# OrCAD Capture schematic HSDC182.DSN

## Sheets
1 PAGE1: size C; title: TUSB2E221QFNEVM; rev: A; note: HSDC182
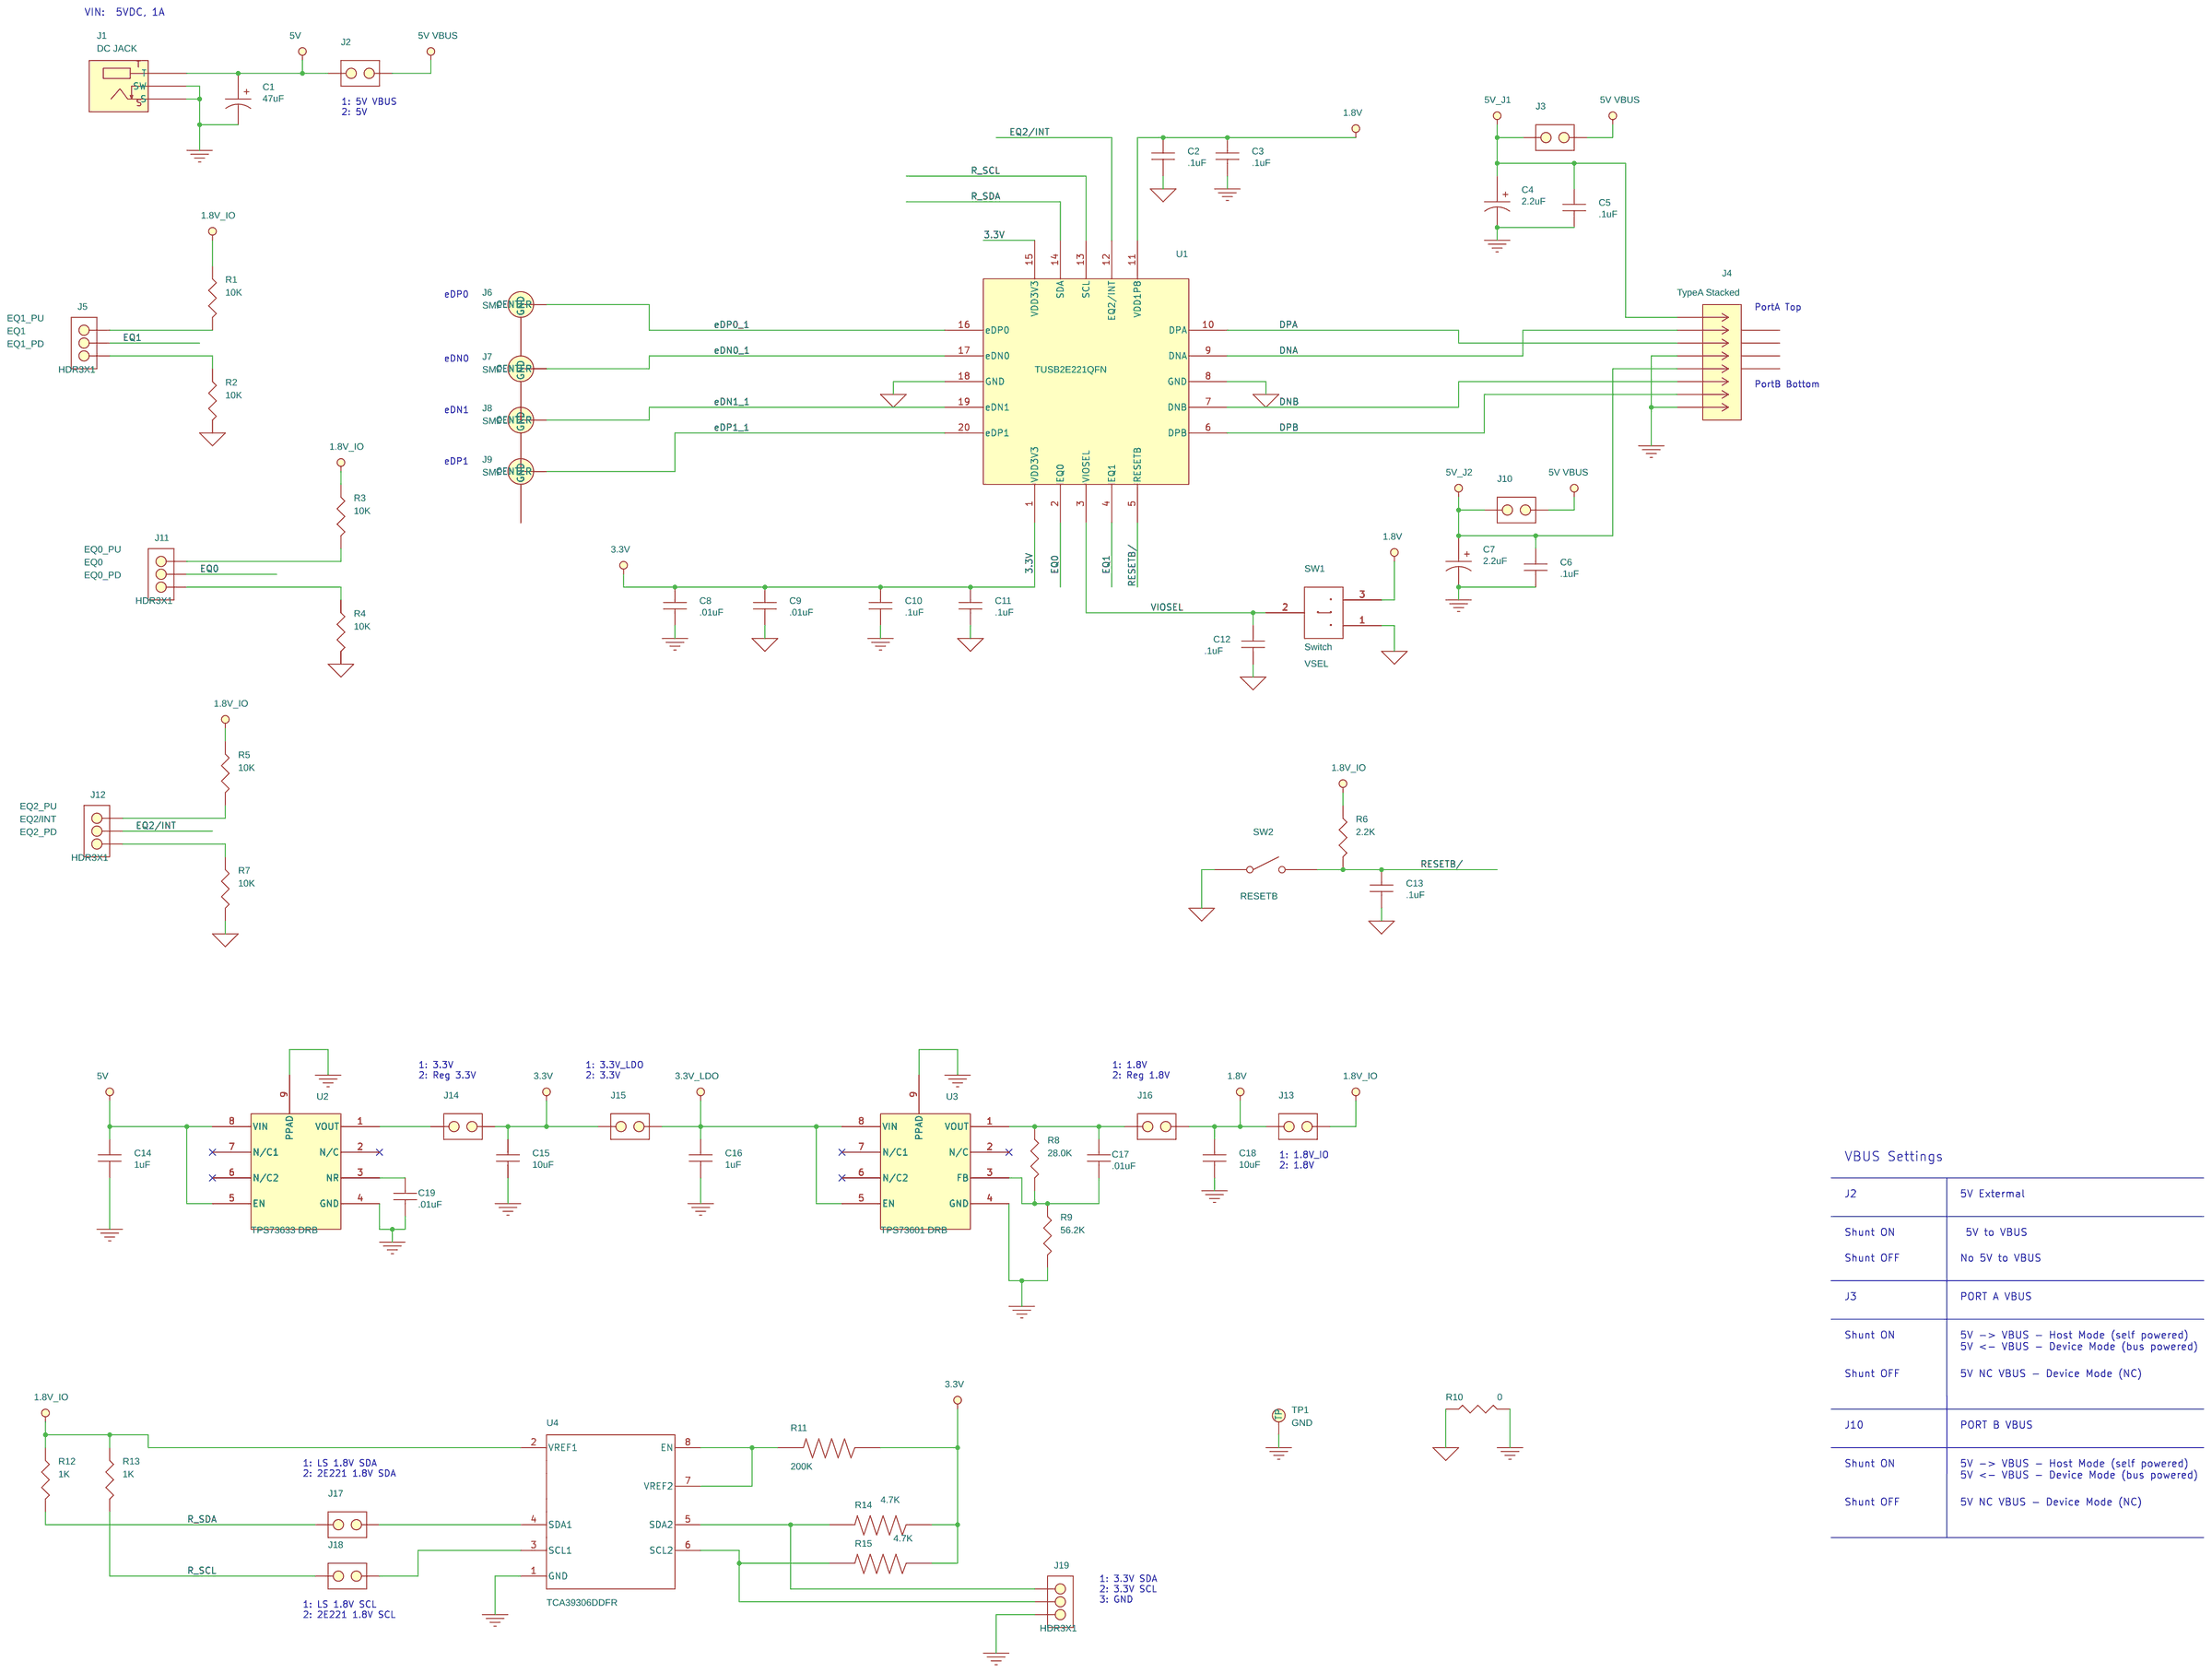
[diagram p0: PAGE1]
2 PAGE2
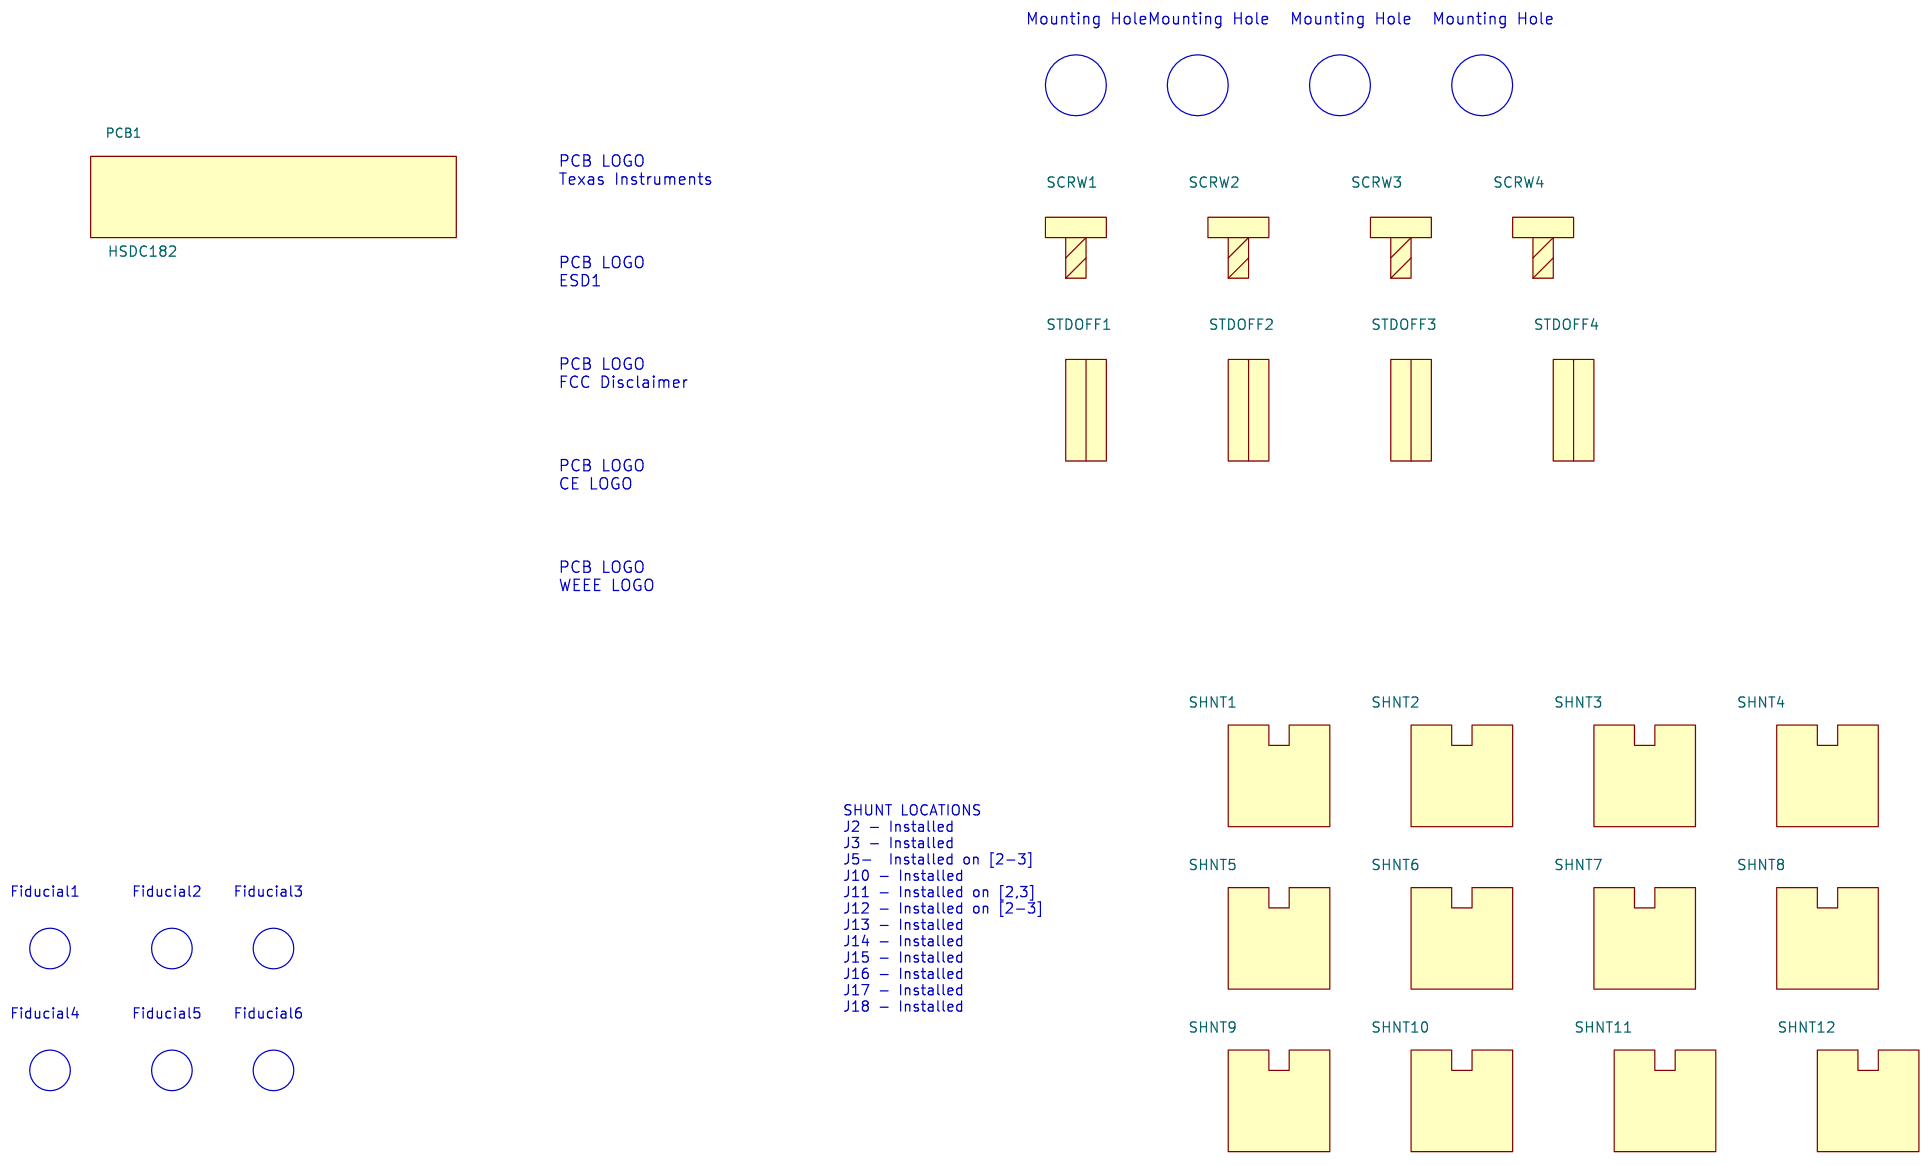
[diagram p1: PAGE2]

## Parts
sheet PAGE1
C1  47uF  [cap_1210]
C2  .1uF  [cap_0402]
C3  .1uF  [cap_0402]
C4  2.2uF  [cap_0805]
C5  .1uF  [cap_0402]
C6  .1uF  [cap_0402]
C7  2.2uF  [cap_0805]
C8  .01uF  [cap_0402]
C9  .01uF  [cap_0402]
C10  .1uF  [cap_0402]
C11  .1uF  [cap_0402]
C12  .1uF  [cap_0402]
C13  .1uF  [cap_0402]
C14  1uF  [cap_0805]
C15  10uF  [cap_0805]
C16  1uF  [cap_0805]
C17  .01uF  [cap_0402]
C18  10uF  [cap_0805]
C19  .01uF  [cap_0402]
J1  DC JACK  [JACK_SMRT_PJ1-022-SMT-TR]
J2  HDR2X1  [HDR_THVT_1X2_254_871]
J3  HDR2X1  [HDR_THVT_1X2_254_871]
J4  TypeA Stacked  [USB-A_THRT_AU-Y1008-2]
J5  HDR3X1  [HDR_THVT_1X3_254_871]
J6  SMP  [CON_SMRT_19S201-40ML5]
J7  SMP  [CON_SMRT_19S201-40ML5]
J8  SMP  [CON_SMRT_19S201-40ML5]
J9  SMP  [CON_SMRT_19S201-40ML5]
J10  HDR2X1  [HDR_THVT_1X2_254_871]
J11  HDR3X1  [HDR_THVT_1X3_254_871]
J12  HDR3X1  [HDR_THVT_1X3_254_871]
J13  HDR2X1  [HDR_THVT_1X2_254_871]
J14  HDR2X1  [HDR_THVT_1X2_254_871]
J15  HDR2X1  [HDR_THVT_1X2_254_871]
J16  HDR2X1  [HDR_THVT_1X2_254_871]
J17  HDR2X1  [HDR_THVT_1X2_254_871]
J18  HDR2X1  [HDR_THVT_1X2_254_871]
J19  HDR3X1  [HDR_THVT_1X3_254_871]
R1  10K  [res_0402]
R2  10K  [res_0402]
R3  10K  [res_0402]
R4  10K  [res_0402]
R5  10K  [res_0402]
R6  2.2K  [res_0402]
R7  10K  [res_0402]
R8  28.0K  [res_0402]
R9  56.2K  [res_0402]
R10  0  [res_0805]
R11  200K  [RES_0402]
R12  1K  [res_0402]
R13  1K  [res_0402]
R14  4.7K  [RES_0402]
R15  4.7K  [RES_0402]
SW1  Switch  [SW_SMVT_CJS-1201B]
SW2  RESETB  [SW_SMVT_B3U-1000P]
TP1  TEST POINT  [HDR_THVT_1X1_871]
U1  TUSB2E221QFN  [VBW0020A]
U2  TPS73633 DRB  [DRB0008BA_150x175]
U3  TPS73601 DRB  [DRB0008BA_150x175]
U4  TCA39306DDFR  [DDF0008A]
sheet PAGE2
PCB1  HSDC182  [n/a]
SCRW1  NY PMS 440 005 PH  [screw]
SCRW2  NY PMS 440 005 PH  [screw]
SCRW3  NY PMS 440 005 PH  [screw]
SCRW4  NY PMS 440 005 PH  [screw]
SHNT1  QPC02SXGN-RC  [.1]
SHNT2  QPC02SXGN-RC  [.1]
SHNT3  QPC02SXGN-RC  [.1]
SHNT4  QPC02SXGN-RC  [.1]
SHNT5  QPC02SXGN-RC  [.1]
SHNT6  QPC02SXGN-RC  [.1]
SHNT7  QPC02SXGN-RC  [.1]
SHNT8  QPC02SXGN-RC  [.1]
SHNT9  QPC02SXGN-RC  [.1]
SHNT10  QPC02SXGN-RC  [.1]
SHNT11  QPC02SXGN-RC  [.1]
SHNT12  QPC02SXGN-RC  [.1]
STDOFF1  1902E  [Standoff]
STDOFF2  1902E  [Standoff]
STDOFF3  1902E  [Standoff]
STDOFF4  1902E  [Standoff]

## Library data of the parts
C1 = CAPACITOR_POL: Digikey: 445-6711-2-ND; Manufacturer: TDK; Manufacturer Part Number: C3225X5R1A476M250AC; SIGNAL_MODEL: DEFAULT_CAPACITOR_4.7e+07pF_1_2
C2 C3 C5 C6 C10-C13 = CAP_NP: Digikey: 311-1336-1-ND; Manufacturer: Yageo; Manufacturer Part Number: CC0402KRX5R6BB104; SIGNAL_MODEL: DEFAULT_CAPACITOR_100000pF_1_2
C4 = CAPACITOR_POL: Digikey: 445-5691-2-ND; Manufacturer: TDK; Manufacturer Part Number: CGA4J3X7R1C225K125AB; SIGNAL_MODEL: DEFAULT_CAPACITOR_2.2e+06pF_1_2
C7 = CAPACITOR_POL: Digikey: 445-5691-2-ND; Diigkey: 445-5691-2-ND; Manufacturer: TDK; Manufacturer Part Number: CGA4J3X7R1C225K125AB; SIGNAL_MODEL: DEFAULT_CAPACITOR_2.2e+06pF_1_2
C8 = CAP_NP: Digikey: 399-1278-2-ND; Diigkey: 399-1278-2-ND; Manufacturer: Kemet; Manufacturer Part Number: C0402C103K3RACTU; SIGNAL_MODEL: DEFAULT_CAPACITOR_10000pF_1_2
C9 C17 C19 = CAP_NP: Digikey: 399-1278-2-ND; Manufacturer: Kemet; Manufacturer Part Number: C0402C103K3RACTU; SIGNAL_MODEL: DEFAULT_CAPACITOR_10000pF_1_2
C14 = CAP_NP: Digikey: 399-1284-2-ND; Manufacturer: Kemet; Manufacturer Part Number: C0805C105K4RACTU; SIGNAL_MODEL: DEFAULT_CAPACITOR_1e+06pF_1_2
C15 C18 = CAP_NP: Digikey: 399-4925-1-ND; Manufacturer: Kemet; Manufacturer Part Number: C0805C106K8PACTU; SIGNAL_MODEL: DEFAULT_CAPACITOR_1e+07pF_1_2
C16 = CAP_NP: Digikey: 399-1284-2-ND; Diigkey: 399-1284-2-ND; Manufacturer: Kemet; Manufacturer Part Number: C0805C105K4RACTU; SIGNAL_MODEL: DEFAULT_CAPACITOR_1e+06pF_1_2
J1 = PWR_JACK: Digikey: CP1-022PJTR-ND; Manufacturer: CUI; Manufacturer Part Number: PJ1-022-SMT-TR
J2 J3 J10 J13-J18 = HDR2X1_M_.1: Digikey: S1012E-02-ND; Manufacturer: Sullins; Manufacturer Part Number: PEC02SAAN
J4 = AU-Y1008-2_0
J5 = HDR3X1_M_.1: Digikey: S1012E-03-ND; Manufacturer: Sullins; Manufacturer Part number: PEC03SAAN; SILKTEXT1: EQ1_PU; SILKTEXT2: EQ1; SILKTEXT3: EQ1_PD
J6-J9 = SMB_0: Digikey: 1868-1133-ND; Manufacturer: Rosenberger; Manufacturer Part Number: 19S201-40ML5
J11 = HDR3X1_M_.1: Digikey: S1012E-03-ND; Manufacturer: Sullins; Manufacturer Part number: PEC03SAAN; SILKTEXT1: EQ0_PU; SILKTEXT2: EQ0; SILKTEXT3: EQ0_PD
J12 = HDR3X1_M_.1: Digikey: S1012E-03-ND; Manufacturer: Sullins; Manufacturer Part number: PEC03SAAN; SILKTEXT1: EQ2_PU; SILKTEXT2: EQ2/INT; SILKTEXT3: EQ2_PD
J19 = HDR3X1_M_.1: Digikey: S1012E-03-ND; Manufacturer: Sullins; Manufacturer Part number: PEC03SAAN; SILKTEXT1: 1: SDA; SILKTEXT2: 2: SCL; SILKTEXT3: 3: GND
R1-R5 R7 = RES: Digikey: 311-10KJRTR-ND; Manufacturer: Yageo; Manufacturer Part Number: RC0402JR-0710KL; SIGNAL_MODEL: DEFAULT_RESISTOR_10000OHM_1_2
R6 = RES: Digikey: 311-2.20KLRTR-ND; Manufacturer: Yageo; Manufacturer Part Number: RC0402FR-072K2L; SIGNAL_MODEL: DEFAULT_RESISTOR_2200OHM_1_2
R8 = RES: Digikey: 311-28.0KLRTR-ND; Manufacturer: Yageo; Manufacturer Part Number: RC0402FR-0728KL; SIGNAL_MODEL: DEFAULT_RESISTOR_28000OHM_1_2
R9 = RES: Digikey: YAG1453TR-ND; Manufacturer: Yageo; Manufacturer Part Number: RT0402BRD0756K2; SIGNAL_MODEL: DEFAULT_RESISTOR_56200OHM_1_2
R10 = RES: Digikey: 311-0.0ARTR-ND; Manufacturer: Yageo; Manufacturer Part Number: RC0805JR-070RL; SIGNAL_MODEL: DEFAULT_RESISTOR_0.001OHM_1_2
R11 = SG73P1ETTP2003D: MANUFACTURER: YAGEO; Manufacturer's Part Number: RC0603FR-07200KL
R12 R13 = RES: Digikey: YAG2306TR-ND; Manufacturer: Yageo; Manufacturer Part Number: RT0402BRE071KL; SIGNAL_MODEL: DEFAULT_RESISTOR_1000.000000OHM_1_2
R14 R15 = RC0402JR-074K7L: MANUFACTURER: YAGEO; Manufacturer's Part Number: RC0603FR-074K7L
SW1 = Switch_CJS-1201: Digikey: 563-1024-1-ND; Manufacturer: Nidec Copal; Manufacturer Part Number: CJS-1201TB; SILKTEXT: VSEL
SW2 = SW_KEY-SPST: Digikey: SW1020CT-ND; Manufacturer: OMRON; Manufacturer Part Number: B3U-1000P
TP1 = Test_Point_Small: Digikey: S1012E-01-ND; Manufacturer: Sullins; Manufacturer Part Number: PEC01SAAN; SILKTEXT: GND
U1 = TUSB2E221QFN: Manufacturer: Texas Instruments
U2 = TPS736_DRB_3: Digikey: 296-17884-1-ND; Manufacturer: Texas Instruments; Manufacturer Part Number: TPS73633DRB
U3 = TPS736_DRB_4: Digikey: 296-27062-1-ND; Manufacturer: Texas Instruments; Manufacturer Part Number: TPS73601DRB
U4 = TCA39306DDFR_0: MANUFACTURER: Texas Instruments
PCB1 = PCB: Manufacturer: Any; Manufacturer Part Number: HSDC124
SCRW1-SCRW4 = Screw_40x.5_Nylon: Digikey: H546-ND; Manufacturer: B&F Fastener; Manufacturer Part Number: NY PMS 440 0050 PH
SHNT1-SHNT12 = Shunt: Digikey: S9337-ND; Manufacturer: Sullins
STDOFF1-STDOFF4 = Standoff: Digikey: 36-1902E-ND; Manufacturer: Keystone

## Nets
1.8V: C2.1 C3.1 C18.1 J13.2 J16.1 SW1.3 U1.11(VDD1P8)
1.8V_IO: J13.1 R1.1 R3.1 R5.1 R6.1 R12.1 R13.1 U4.2(VREF1)
3.3V: C8.1 C9.1 C10.1 C11.1 C15.1 J14.1 J15.2 R11.2 R14.2 R15.2 U1.1(VDD3V3) U1.15(VDD3V3)
3.3V_LDO: C16.1 J15.1 U3.5(EN) U3.8(VIN)
5V: C1.1 C14.1 J1.1(T) J2.2 U2.5(EN) U2.8(VIN)
5V VBUS: J2.1 J3.1 J10.1
5V_J1: C4.1 C5.1 J3.2 J4.1
5V_J2: C6.1 C7.1 J4.5 J10.2
GND: C1.2 C3.2 C4.2 C5.2 C6.2 C7.2 C8.2 C10.2 C14.2 C15.2 C16.2 C18.2 C19.2 J1.2(S) J1.3(SW) J4.4 J4.8 J6.2(GND) J7.2(GND) J8.2(GND) J9.2(GND) J19.3 R9.2 R10.2 TP1.1(TP) U2.4(GND) U2.9(PPAD) U3.4(GND) U3.9(PPAD) U4.1(GND)
GND_SIGNAL: C2.2 C9.2 C11.2 C12.2 C13.2 R2.2 R4.2 R7.2 R10.1 SW1.1 SW2.1 U1.8(GND) U1.18(GND)
DNA: J4.2 U1.9(DNA)
DNB: J4.6 U1.7(DNB)
DPA: J4.3 U1.10(DPA)
DPB: J4.7 U1.6(DPB)
eDN0_1: J7.1(CENTER) U1.17(eDN0)
eDN1_1: J8.1(CENTER) U1.19(eDN1)
eDP0_1: J6.1(CENTER) U1.16(eDP0)
eDP1_1: J9.1(CENTER) U1.20(eDP1)
EQ0: J11.2 U1.2(EQ0)
EQ1: J5.2 U1.4(EQ1)
EQ2/INT: J12.2 U1.12(EQ2/INT)
R_SCL: J18.2 R13.2 U1.13(SCL)
R_SDA: J17.2 R12.2 U1.14(SDA)
RESETB/: C13.1 R6.2 SW2.2 U1.5(RESETB)
VIOSEL: C12.1 SW1.2 U1.3(VIOSEL)
N16778222: J5.1 R1.2
N16778248: J5.3 R2.1
N16778386: J11.1 R3.2
N16778440: J11.3 R4.1
N16778562: J12.1 R5.2
N16778631: J12.3 R7.1
N16778928: J14.2 U2.1(VOUT)
N16778948: C17.1 J16.2 R8.1 U3.1(VOUT)
N16779019: C19.1 U2.3(NR)
N16779025: C17.2 R8.2 R9.1 U3.3(FB)
N16794481: J17.1 U4.4(SDA1)
N16794484: J18.1 U4.3(SCL1)
N16794750: R11.1 U4.7(VREF2) U4.8(EN)
N16794768: J19.1 R14.1 U4.5(SDA2)
N16794775: J19.2 R15.1 U4.6(SCL2)

Not connected (* = marked no-connect by the designer): J4 9 10 11 12; U2 2(N/C)* 6(N/C2)* 7(N/C1)*; U3 2(N/C)* 6(N/C2)* 7(N/C1)*

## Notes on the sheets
sheet 1
- VIN:  5VDC, 1A
- 1: 5V VBUS
  2: 5V
- eDP0
- PortA Top
- eDN0
- PortB Bottom
- eDN1
- eDP1
- 1: 3.3V
  2: Reg 3.3V
- 1: 3.3V_LDO
  2: 3.3V
- 1: 1.8V
  2: Reg 1.8V
- 1: 1.8V_IO
  2: 1.8V
- VBUS Settings
- J2
- 5V Extermal
- Shunt ON
- 5V to VBUS
- Shunt OFF
- No 5V to VBUS
- J3
- PORT A VBUS
- Shunt ON
- 5V -> VBUS - Host Mode (self powered)
  5V <- VBUS - Device Mode (bus powered)
- Shunt OFF
- 5V NC VBUS - Device Mode (NC)
- J10
- PORT B VBUS
- 1: LS 1.8V SDA
  2: 2E221 1.8V SDA
- Shunt ON
- 5V -> VBUS - Host Mode (self powered)
  5V <- VBUS - Device Mode (bus powered)
- Shunt OFF
- 5V NC VBUS - Device Mode (NC)
- 1: 3.3V SDA
  2: 3.3V SCL
  3: GND
- 1: LS 1.8V SCL
  2: 2E221 1.8V SCL
sheet 2
- Mounting Hole
- Mounting Hole
- Mounting Hole
- Mounting Hole
- PCB LOGO
  Texas Instruments
- PCB LOGO
  ESD1
- PCB LOGO
  FCC Disclaimer
- PCB LOGO
  CE LOGO
- PCB LOGO
  WEEE LOGO
- SHUNT LOCATIONS
  J2 - Installed
  J3 - Installed
  J5-  Installed on [2-3]
  J10 - Installed
  J11 - Installed on [2,3]
  J12 - Installed on [2-3]
  J13 - Installed
  J14 - Installed
  J15 - Installed
  J16 - Installed
  J17 - Installed
  J18 - Installed
- Fiducial1
- Fiducial2
- Fiducial3
- Fiducial4
- Fiducial5
- Fiducial6
